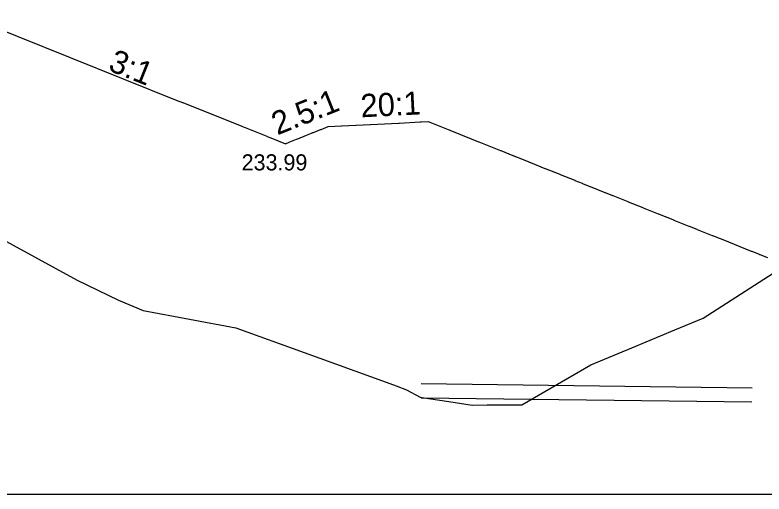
# Model space of a CAD drawing. Extents: x -26 to 1629, y -25 to 9635.
# Drawn here: x 312.2 to 417, y 6500 to 6567 of the extents above; entities that cross this region are included whole.
import ezdxf

# ---------------------------------------------------------------- set-up
doc = ezdxf.new("R2010")
doc.units = 0
for name, color, linetype in [('DTM CONTOURS_MAJOR', 7, 'Continuous'), ('DTM_X_GROUND', 7, 'Continuous'), ('XS_CELL', 7, 'Continuous'), ('XS_P_DRAINAGE', 7, 'Continuous'), ('XS_P_GROUND', 7, 'Continuous'), ('XS_P_TX_DCH', 7, 'Continuous'), ('XS_P_TX_FS_BS', 7, 'Continuous')]:
    doc.layers.add(name, color=color, linetype=linetype)

msp = doc.modelspace()

# ---------------------------------------------------------------- linework, layer by layer
at = {"layer": 'DTM_X_GROUND'}
msp.add_lwpolyline([(279.53, 6552.46), (320.87, 6529.91), (326.64, 6527.12), (330.12, 6525.67), (343.05, 6523.25), (352.65, 6519.78), (364.11, 6515.64), (365.51, 6515.11), (366.95, 6514.59), (368.89, 6513.54), (370.03, 6513.37), (372.88, 6512.93), (376.14, 6512.43), (378.25, 6512.46), (383.12, 6512.48), (392.77, 6518.08), (398.5, 6520.45), (404.52, 6522.94), (408.51, 6524.59), (420.23, 6532.15)], dxfattribs=at)
at = {"layer": 'XS_CELL'}
msp.add_line((100, 6500), (550, 6500), dxfattribs=at)
at = {"layer": 'XS_P_DRAINAGE'}
for p, q in [((369.02, 6515.45), (415.33, 6514.87)), ((369, 6513.45), (415.3, 6512.87))]:
    msp.add_line(p, q, dxfattribs=at)
at = {"layer": 'XS_P_GROUND'}
msp.add_lwpolyline([(305, 6566.99), (334.73, 6555.09), (335.59, 6554.75), (335.65, 6554.73), (343.89, 6551.43), (344, 6551.39), (344.25, 6551.29), (344.36, 6551.24), (347.39, 6550.03), (347.47, 6550), (347.97, 6549.8), (350, 6548.99), (350.53, 6549.2), (350.61, 6549.23), (351.58, 6549.62), (351.74, 6549.68), (352.95, 6550.16), (353.67, 6550.45), (353.85, 6550.53), (353.93, 6550.56), (353.95, 6550.57), (354.91, 6550.95), (355, 6550.99), (356, 6551.39), (357.88, 6551.48), (357.93, 6551.48), (359.86, 6551.58), (359.91, 6551.58), (361.85, 6551.68), (361.93, 6551.68), (364.85, 6551.83), (364.88, 6551.83), (365.86, 6551.88), (365.93, 6551.88), (368.88, 6552.03), (369.01, 6552.04), (370, 6552.09), (370.91, 6551.72), (372.81, 6550.96), (372.94, 6550.91), (373.01, 6550.88), (376, 6549.68), (376.03, 6549.67), (377.02, 6549.27), (377.1, 6549.24), (380.11, 6548.04), (380.15, 6548.02), (381.86, 6547.33), (381.87, 6547.33), (382.18, 6547.21), (382.22, 6547.19), (383.98, 6546.49), (383.98, 6546.48), (384.25, 6546.38), (384.3, 6546.36), (386.33, 6545.54), (386.38, 6545.52), (388.42, 6544.71), (388.47, 6544.69), (390.52, 6543.87), (390.54, 6543.86), (391.57, 6543.45), (391.6, 6543.43), (392.62, 6543.02), (392.68, 6543), (394.74, 6542.18), (394.76, 6542.17), (395.8, 6541.75), (395.85, 6541.73), (397.92, 6540.9), (397.97, 6540.88), (400.06, 6540.05), (400.11, 6540.03), (402.2, 6539.19), (402.22, 6539.18), (403.27, 6538.76), (403.3, 6538.75), (404.35, 6538.33), (404.4, 6538.31), (406.5, 6537.46), (406.53, 6537.45), (407.59, 6537.03), (407.64, 6537.01), (409.76, 6536.16), (409.81, 6536.14), (411.93, 6535.29), (412.01, 6535.26), (415.22, 6533.97), (415.22, 6533.97), (415.27, 6533.95), (415.3, 6533.94), (416.32, 6533.53), (416.32, 6533.53), (416.38, 6533.51), (416.4, 6533.5), (417.48, 6533.07)], dxfattribs=at)

# ---------------------------------------------------------------- texts
at = {"layer": 'DTM CONTOURS_MAJOR'}
for p in [(343.96, 6551.33), (355.96, 6551.33), (369.96, 6552.03), (349.96, 6548.93)]:
    msp.add_text('X', height=0.12, dxfattribs=at).set_placement(p)
at = {"layer": 'XS_P_TX_DCH'}
msp.add_text('233.99', height=2.25, dxfattribs=at).set_placement((343.88, 6545.25))
at = {"layer": 'XS_P_TX_FS_BS'}
for s, rotation, p in [('3:1', 338.1986, (325.05, 6559.29)), ('2.5:1', 21.8014, (348.88, 6550.14)), ('20:1', 2.8624, (360.6, 6552.67))]:
    msp.add_text(s, height=3.24, rotation=rotation, dxfattribs=at).set_placement(p)

doc.saveas('drawing.dxf')
